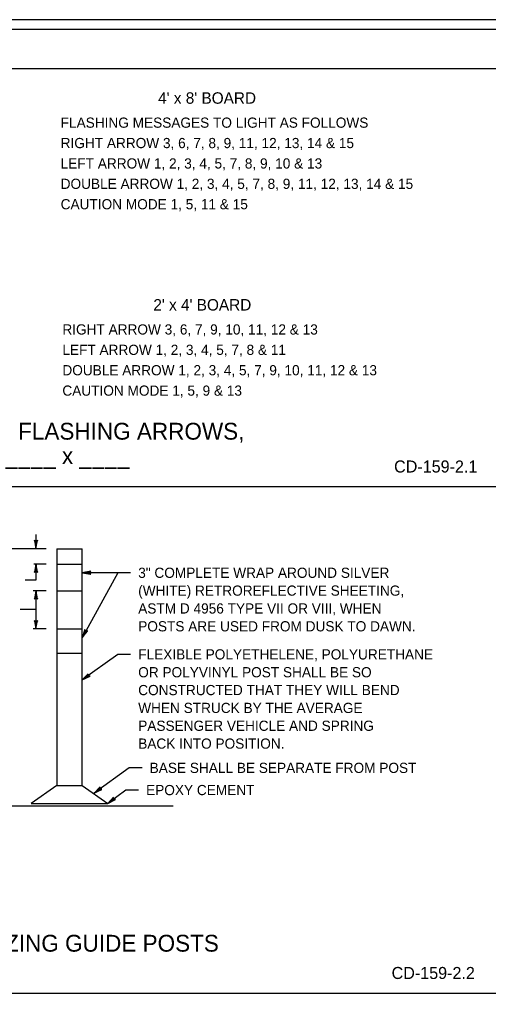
# Model space of a CAD drawing. Extents: x 499940 to 501012, y 499990 to 500649.
# Drawn here: x 500151.3 to 500335, y 500259.8 to 500649.2 of the extents above; entities that cross this region are included whole.
import ezdxf

# ---------------------------------------------------------------- set-up
doc = ezdxf.new("R2010")
doc.units = 0
for name, color, linetype in [('1', 7, 'Continuous'), ('10', 7, 'Continuous'), ('24', 7, 'Continuous'), ('41', 7, 'Continuous'), ('5', 7, 'Continuous')]:
    doc.layers.add(name, color=color, linetype=linetype)

msp = doc.modelspace()

# ---------------------------------------------------------------- linework, layer by layer
at = {"layer": '1'}
msp.add_line((500990, 500630), (500000, 500630), dxfattribs=at)
msp.add_lwpolyline([(499956.44, 500645.46), (500590.04, 500645.46), (501001.61, 500645.46)], dxfattribs=at)
at = {"layer": '10'}
for p, q in [((500000, 500466.05), (500339.52, 500466.05)), ((500000, 500267.34), (500339.52, 500267.34))]:
    msp.add_line(p, q, dxfattribs=at)
at = {"layer": '24'}
for points in [[(500157.65, 500441.65), (500158.24, 500444.98), (500157.65, 500444.18), (500157.07, 500444.96), (500157.65, 500441.65), (500157.65, 500441.88), (500158.2, 500444.88), (500157.65, 500444.12), (500157.12, 500444.83), (500157.64, 500441.99), (500157.65, 500442.1), (500158.11, 500444.68), (500157.65, 500444.1), (500157.19, 500444.7), (500157.65, 500442.16), (500157.64, 500442.27), (500158.04, 500444.52), (500157.65, 500444.08), (500157.25, 500444.53), (500157.64, 500442.59), (500157.64, 500442.77), (500157.96, 500444.35), (500157.66, 500444.05), (500157.33, 500444.38), (500157.65, 500442.81), (500157.66, 500442.99), (500157.87, 500444.17), (500157.64, 500443.94), (500157.41, 500444.19), (500157.65, 500443.15), (500157.67, 500443.32), (500157.81, 500444.03), (500157.65, 500443.91), (500157.47, 500444.11), (500157.65, 500443.4), (500157.76, 500443.87), (500157.64, 500443.8), (500157.51, 500444), (500157.64, 500443.52), (500157.71, 500443.82), (500157.61, 500443.7), (500157.55, 500443.84), (500157.65, 500443.7), (500157.66, 500443.77)], [(500157.65, 500435.66), (500157.06, 500432.33), (500157.65, 500433.13), (500158.23, 500432.35), (500157.65, 500435.66), (500157.66, 500435.44), (500157.11, 500432.43), (500157.66, 500433.19), (500158.19, 500432.49), (500157.67, 500435.32), (500157.65, 500435.21), (500157.19, 500432.63), (500157.66, 500433.21), (500158.11, 500432.61), (500157.65, 500435.16), (500157.67, 500435.05), (500157.26, 500432.79), (500157.65, 500433.23), (500158.06, 500432.78), (500157.67, 500434.73), (500157.67, 500434.54), (500157.35, 500432.96), (500157.64, 500433.27), (500157.97, 500432.94), (500157.65, 500434.51), (500157.64, 500434.33), (500157.44, 500433.14), (500157.67, 500433.37), (500157.9, 500433.12), (500157.65, 500434.16), (500157.64, 500434), (500157.5, 500433.28), (500157.66, 500433.4), (500157.84, 500433.21), (500157.65, 500433.91), (500157.54, 500433.45), (500157.67, 500433.51), (500157.8, 500433.31), (500157.67, 500433.79), (500157.59, 500433.49), (500157.69, 500433.62), (500157.75, 500433.47), (500157.66, 500433.62), (500157.64, 500433.54)], [(500175.77, 500432.23), (500179.12, 500431.63), (500178.32, 500432.23), (500179.11, 500432.81), (500175.77, 500432.23), (500176, 500432.23), (500179.03, 500431.68), (500178.26, 500432.23), (500178.97, 500432.76), (500176.12, 500432.24), (500176.23, 500432.23), (500178.83, 500431.77), (500178.24, 500432.23), (500178.84, 500432.69), (500176.28, 500432.23), (500176.39, 500432.24), (500178.66, 500431.83), (500178.22, 500432.23), (500178.67, 500432.64), (500176.71, 500432.24), (500176.9, 500432.24), (500178.49, 500431.92), (500178.18, 500432.22), (500178.52, 500432.55), (500176.94, 500432.23), (500177.12, 500432.22), (500178.31, 500432.01), (500178.08, 500432.24), (500178.33, 500432.47), (500177.28, 500432.23), (500177.45, 500432.21), (500178.17, 500432.07), (500178.05, 500432.23), (500178.24, 500432.41), (500177.54, 500432.23), (500178, 500432.12), (500177.94, 500432.24), (500178.14, 500432.37), (500177.65, 500432.24), (500177.96, 500432.17), (500177.83, 500432.27), (500177.98, 500432.33), (500177.83, 500432.23), (500177.91, 500432.22)], [(500157.65, 500425.17), (500157.06, 500421.84), (500157.65, 500422.64), (500158.23, 500421.86), (500157.65, 500425.17), (500157.66, 500424.95), (500157.11, 500421.94), (500157.66, 500422.7), (500158.19, 500421.99), (500157.67, 500424.83), (500157.65, 500424.72), (500157.19, 500422.14), (500157.66, 500422.72), (500158.11, 500422.12), (500157.65, 500424.67), (500157.67, 500424.56), (500157.26, 500422.3), (500157.65, 500422.74), (500158.06, 500422.29), (500157.67, 500424.23), (500157.67, 500424.05), (500157.35, 500422.47), (500157.64, 500422.78), (500157.97, 500422.44), (500157.65, 500424.01), (500157.64, 500423.84), (500157.44, 500422.65), (500157.67, 500422.88), (500157.9, 500422.63), (500157.65, 500423.67), (500157.64, 500423.5), (500157.5, 500422.79), (500157.66, 500422.91), (500157.84, 500422.72), (500157.65, 500423.42), (500157.54, 500422.95), (500157.67, 500423.02), (500157.8, 500422.82), (500157.67, 500423.3), (500157.59, 500423), (500157.69, 500423.12), (500157.75, 500422.98), (500157.66, 500423.12), (500157.64, 500423.05)], [(500157.65, 500410.18), (500158.24, 500413.5), (500157.65, 500412.71), (500157.07, 500413.48), (500157.65, 500410.18), (500157.65, 500410.4), (500158.2, 500413.41), (500157.65, 500412.65), (500157.12, 500413.35), (500157.64, 500410.52), (500157.65, 500410.63), (500158.11, 500413.21), (500157.65, 500412.63), (500157.19, 500413.22), (500157.65, 500410.68), (500157.64, 500410.79), (500158.04, 500413.04), (500157.65, 500412.61), (500157.25, 500413.05), (500157.64, 500411.11), (500157.64, 500411.3), (500157.96, 500412.88), (500157.66, 500412.57), (500157.33, 500412.9), (500157.65, 500411.33), (500157.66, 500411.51), (500157.87, 500412.7), (500157.64, 500412.47), (500157.41, 500412.72), (500157.65, 500411.67), (500157.67, 500411.84), (500157.81, 500412.55), (500157.65, 500412.43), (500157.47, 500412.63), (500157.65, 500411.93), (500157.76, 500412.39), (500157.64, 500412.32), (500157.51, 500412.53), (500157.64, 500412.04), (500157.71, 500412.35), (500157.61, 500412.22), (500157.55, 500412.37), (500157.65, 500412.22), (500157.66, 500412.3)], [(500175.77, 500406.76), (500177.9, 500409.42), (500177, 500409), (500176.87, 500409.97), (500175.77, 500406.76), (500175.88, 500406.96), (500177.82, 500409.35), (500176.96, 500408.95), (500176.84, 500409.82), (500175.92, 500407.07), (500175.99, 500407.16), (500177.65, 500409.22), (500176.96, 500408.93), (500176.85, 500409.68), (500176.02, 500407.21), (500176.06, 500407.31), (500177.51, 500409.11), (500176.95, 500408.91), (500176.81, 500409.5), (500176.21, 500407.6), (500176.3, 500407.76), (500177.35, 500409), (500176.94, 500408.87), (500176.81, 500409.32), (500176.33, 500407.78), (500176.43, 500407.93), (500177.18, 500408.88), (500176.87, 500408.79), (500176.79, 500409.12), (500176.5, 500408.08), (500176.59, 500408.22), (500177.06, 500408.79), (500176.86, 500408.76), (500176.8, 500409.02), (500176.62, 500408.31), (500176.94, 500408.66), (500176.8, 500408.67), (500176.79, 500408.91), (500176.66, 500408.42), (500176.88, 500408.65), (500176.73, 500408.59), (500176.75, 500408.75), (500176.76, 500408.57), (500176.81, 500408.63)], [(500175.77, 500390.18), (500178.84, 500391.65), (500177.84, 500391.66), (500178.14, 500392.59), (500175.77, 500390.18), (500175.95, 500390.31), (500178.74, 500391.63), (500177.79, 500391.63), (500178.06, 500392.48), (500176.04, 500390.39), (500176.14, 500390.44), (500178.52, 500391.58), (500177.78, 500391.62), (500178, 500392.34), (500176.18, 500390.47), (500176.27, 500390.55), (500178.35, 500391.54), (500177.76, 500391.6), (500177.89, 500392.2), (500176.53, 500390.74), (500176.68, 500390.85), (500178.16, 500391.51), (500177.74, 500391.57), (500177.81, 500392.04), (500176.72, 500390.85), (500176.87, 500390.95), (500177.96, 500391.48), (500177.64, 500391.54), (500177.71, 500391.87), (500177, 500391.06), (500177.14, 500391.14), (500177.81, 500391.45), (500177.62, 500391.51), (500177.67, 500391.77), (500177.21, 500391.2), (500177.65, 500391.39), (500177.52, 500391.45), (500177.61, 500391.68), (500177.29, 500391.29), (500177.59, 500391.4), (500177.42, 500391.41), (500177.51, 500391.55), (500177.44, 500391.38), (500177.51, 500391.42)], [(500180.47, 500345.8), (500183.51, 500347.27), (500182.53, 500347.28), (500182.82, 500348.2), (500180.47, 500345.8), (500180.65, 500345.94), (500183.41, 500347.25), (500182.47, 500347.25), (500182.74, 500348.09), (500180.74, 500346.02), (500180.84, 500346.07), (500183.2, 500347.2), (500182.46, 500347.24), (500182.68, 500347.95), (500180.88, 500346.1), (500180.96, 500346.17), (500183.03, 500347.16), (500182.44, 500347.22), (500182.57, 500347.81), (500181.22, 500346.36), (500181.37, 500346.47), (500182.84, 500347.13), (500182.42, 500347.19), (500182.5, 500347.65), (500181.41, 500346.48), (500181.56, 500346.57), (500182.64, 500347.1), (500182.32, 500347.15), (500182.39, 500347.48), (500181.69, 500346.68), (500181.83, 500346.76), (500182.49, 500347.07), (500182.3, 500347.13), (500182.36, 500347.38), (500181.89, 500346.82), (500182.33, 500347.01), (500182.21, 500347.07), (500182.3, 500347.29), (500181.98, 500346.91), (500182.27, 500347.02), (500182.11, 500347.03), (500182.19, 500347.16), (500182.13, 500347), (500182.2, 500347.03)], [(500185.77, 500341.73), (500188.81, 500343.25), (500187.81, 500343.25), (500188.09, 500344.19), (500185.77, 500341.73), (500185.94, 500341.87), (500188.71, 500343.23), (500187.76, 500343.22), (500188.01, 500344.07), (500186.03, 500341.95), (500186.13, 500342), (500188.49, 500343.18), (500187.74, 500343.21), (500187.95, 500343.93), (500186.17, 500342.03), (500186.25, 500342.11), (500188.32, 500343.14), (500187.73, 500343.19), (500187.85, 500343.79), (500186.51, 500342.3), (500186.66, 500342.42), (500188.13, 500343.1), (500187.71, 500343.16), (500187.78, 500343.63), (500186.7, 500342.42), (500186.85, 500342.52), (500187.93, 500343.07), (500187.61, 500343.12), (500187.67, 500343.45), (500186.98, 500342.63), (500187.12, 500342.72), (500187.78, 500343.03), (500187.59, 500343.09), (500187.64, 500343.35), (500187.18, 500342.78), (500187.62, 500342.97), (500187.49, 500343.03), (500187.58, 500343.26), (500187.27, 500342.87), (500187.56, 500342.99), (500187.39, 500342.99), (500187.48, 500343.13), (500187.42, 500342.96), (500187.49, 500343)]]:
    msp.add_lwpolyline(points, dxfattribs=at)
at = {"layer": '41'}
msp.add_lwpolyline([(499939.98, 499990.18), (501000.54, 499990.18), (501000.54, 500649.16), (499939.98, 500649.16)], close=True, dxfattribs=at)
at = {"layer": '5'}
for p, q in [((500157.65, 500447.2), (500157.65, 500441.65)), ((500161.65, 500441.65), (500131.99, 500441.65)), ((500165.78, 500441.65), (500175.77, 500441.65)), ((500165.78, 500441.65), (500165.78, 500348.73)), ((500175.77, 500348.73), (500175.77, 500441.65)), ((500161.65, 500435.66), (500156.8, 500435.66)), ((500157.65, 500435.66), (500157.65, 500429.37)), ((500165.78, 500435.66), (500175.77, 500435.66)), ((500157.65, 500429.37), (500153.4, 500429.37)), ((500189.74, 500432.23), (500175.77, 500432.23)), ((500161.65, 500425.17), (500156.5, 500425.17)), ((500157.65, 500425.17), (500157.65, 500410.18)), ((500165.78, 500425.17), (500175.77, 500425.17)), ((500157.65, 500417.84), (500151.47, 500417.84)), ((500161.65, 500410.18), (500156.5, 500410.18)), ((500165.78, 500410.18), (500175.77, 500410.18)), ((500165.78, 500400.69), (500175.77, 500400.69)), ((500165.78, 500348.73), (500155.79, 500341.73)), ((500165.78, 500348.73), (500175.77, 500348.73)), ((500175.77, 500348.73), (500185.77, 500341.73)), ((500128.06, 500340.73), (500211.46, 500340.73)), ((500155.79, 500341.73), (500185.77, 500341.73))]:
    msp.add_line(p, q, dxfattribs=at)
for points in [[(500194.74, 500432.23), (500189.74, 500432.23), (500175.77, 500406.76)], [(500194.74, 500400.21), (500189.74, 500400.21), (500175.77, 500390.18)], [(500199.23, 500355.69), (500194.24, 500355.69), (500180.47, 500345.8)], [(500197.83, 500346.98), (500192.83, 500346.98), (500185.77, 500341.73)]]:
    msp.add_lwpolyline(points, dxfattribs=at)

# ---------------------------------------------------------------- texts
for s, height, p in [("4' x 8' BOARD", 4.5, (500205.54, 500616.24)), ('FLASHING MESSAGES TO LIGHT AS FOLLOWS', 4, (500167.33, 500606.83)), ('RIGHT ARROW 3, 6, 7, 8, 9, 11, 12, 13, 14 & 15', 4, (500167.33, 500598.83)), ('LEFT ARROW 1, 2, 3, 4, 5, 7, 8, 9, 10 & 13', 4, (500167.33, 500590.83)), ('DOUBLE ARROW 1, 2, 3, 4, 5, 7, 8, 9, 11, 12, 13, 14 & 15', 4, (500167.33, 500582.83)), ('CAUTION MODE 1, 5, 11 & 15', 4, (500167.33, 500574.83)), ("2' x 4' BOARD", 4.5, (500203.68, 500535.11)), ('RIGHT ARROW 3, 6, 7, 9, 10, 11, 12 & 13', 4, (500168, 500525.7)), ('LEFT ARROW 1, 2, 3, 4, 5, 7, 8 & 11', 4, (500168, 500517.7)), ('DOUBLE ARROW 1, 2, 3, 4, 5, 7, 9, 10, 11, 12 & 13', 4, (500168, 500509.7)), ('CAUTION MODE 1, 5, 9 & 13', 4, (500168, 500501.7)), ('ILLUMINATED FLASHING ARROWS,', 6.6001, (500089.83, 500484.46)), ('____ x ____', 6.6001, (500145.74, 500474.86)), ('CD-159-2.1', 4.724, (500298.1, 500471.56)), ('3" COMPLETE WRAP AROUND SILVER', 4, (500197.74, 500430.23)), ('(WHITE) RETROREFLECTIVE SHEETING,', 4, (500197.74, 500423.23)), ('ASTM D 4956 TYPE VII OR VIII, WHEN', 4, (500197.74, 500416.23)), ('POSTS ARE USED FROM DUSK TO DAWN.', 4, (500197.74, 500409.23)), ('FLEXIBLE POLYETHELENE, POLYURETHANE', 4, (500197.74, 500398.21)), ('OR POLYVINYL POST SHALL BE SO', 4, (500197.74, 500391.21)), ('CONSTRUCTED THAT THEY WILL BEND', 4, (500197.74, 500384.21)), ('WHEN STRUCK BY THE AVERAGE', 4, (500197.74, 500377.21)), ('PASSENGER VEHICLE AND SPRING', 4, (500197.74, 500370.21)), ('BACK INTO POSITION.', 4, (500197.74, 500363.21)), ('BASE SHALL BE SEPARATE FROM POST', 4, (500202.23, 500353.69)), ('EPOXY CEMENT', 4, (500200.83, 500344.98)), ('CHANNELIZING GUIDE POSTS', 6.6001, (500100.89, 500283.58)), ('CD-159-2.2', 4.724, (500297.12, 500272.85))]:
    msp.add_text(s, height=height, dxfattribs=at).set_placement(p)

doc.saveas('drawing.dxf')
